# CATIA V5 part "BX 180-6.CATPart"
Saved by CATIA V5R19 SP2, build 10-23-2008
Part number: BX 180-6
Bounding box of the stored display mesh (mm): x -24.865 to 24.865, y -24.997 to 24.997, z 0 to 66
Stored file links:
  C:\Users\Bora\Desktop\3D Katı model\BX serisi\BX 180\BX 180-6.CATPart
  C:\Program Files\Dassault Systemes\B19\intel_a\reffiles\standard\MetricThinPitch.txt
  C:\Program Files\Dassault Systemes\B19\intel_a\reffiles\standard\MetricThickPitch.txt
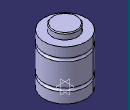
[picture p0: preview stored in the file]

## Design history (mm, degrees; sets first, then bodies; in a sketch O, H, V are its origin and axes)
Body1 (main body)
  Sketch1 on yz-plane, origin (0, 0, 0), H (0, 1, 0), V (0, 0, 1)
    point P2 (25, 12.5)
    line L1 (25, 12.5) -> (25, 0)
    point P3 (25, 16.5)
    point P4 (25, 43.5)
    line L2 (25, 43.5) -> (25, 16.5)
    point P6 (15, 65)
    arc A1 centre (14, 65) radius 1 from (15, 65) to (14, 66) ccw
    point P8 (15, 65)
    line L3 (15, 65) -> (15, 59)
    point P9 (25, 47.5)
    line L4 (25, 59) -> (25, 47.5)
    point P11 (25, 43.5)
    point P12 (25, 47.5)
    arc A2 centre (25, 45.5) radius 2 from (25, 47.5) to (25, 43.5) ccw
    point P13 (25, 12.5)
    point P14 (25, 16.5)
    arc A3 centre (25, 14.5) radius 2 from (25, 16.5) to (25, 12.5) ccw
    line L5 (14, 66) -> (0, 66)
    point P15 (0, 66)
    line L6 (15, 59) -> (25, 59)
    line L7 (25, 0) -> (0, 0)
    coincidence: P15 V, P2 P13, P3 P14, P4 P11, P6 P8, P9 P12
    horizontal: L5 H, L6 H, L7 H
  Shaft1: profile Sketch1, axis Sketch1.V, angle 360
  Sketch2 on face of Shaft1 from Sketch1.L7, origin (0, 0, 0), H (1, 0, 0), V (0, -1, 0)
    point P1 (12.5, 0)
    distance P1 V = 12.5
  Hole1: placed by Sketch2, at (12.5, 0, 0) direction (0, 0, 1), diameter 4.917, depth 6, threaded "M6", thread diameter 6, thread depth 6, pitch 1
  Sketch3 on face of Shaft1 from Sketch1.L7, origin (0, 0, 0), H (1, 0, 0), V (0, -1, 0)
    point P1 (-12.5, 0)
    distance P1 V = 12.5
  Hole2: placed by Sketch3, at (-12.5, 0, 0) direction (0, 0, 1), diameter 4.917, depth 6, threaded "M6", thread diameter 6, thread depth 6, pitch 1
